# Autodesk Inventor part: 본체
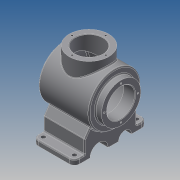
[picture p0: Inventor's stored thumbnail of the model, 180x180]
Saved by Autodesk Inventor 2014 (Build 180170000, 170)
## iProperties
Created: 2018-08
Part Number: 본체
Material: Generic
Document SubType Name: Modeling
Designer: kb542
Density: 1 g/cm^3
Appearance: Default
Author: kb542
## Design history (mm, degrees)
sketch "스케치1"
  geometry: L1 (-60, 0)-(60, 0); L2 (-60, 38)-(-48, 38); L3 (-48, 38)-(-48, 50); L4 (-48, 50)-(48.671, 50); L5 (42.163, 40)-(-38, 40); L6 (-38, 40)-(-38, 27); L7 (-38, 27)-(-60, 27); L8 (-60, 27)-(-60, 38); A1 r 116 centre (-56, 0) between (60, 0) and (48.671, 50); A2 r 106 centre (-56, 0) between (50, 0) and (42.163, 40); 2 further points
  constraints: 16 end point, 4 parallel, 4 point on circle, 3 perpendicular, 2 centre point, 2 point on line, 1 coincident, 1 horizontal, 1 midpoint, 1 vertical alignment
  dimensions: "d0" = 116 radius of A1; "d1" = 76 diameter of L2 L1; "d2" = 100 diameter of L4 L1; "d3" = 12 distance of L2.start L2.end; "d5" = 108 distance from line of L1.end L3; "d6" = 10 radial gap between concentric circles of A2 A1; "d7" = 54 diameter of L7 L1; "d8" = 80 diameter of L5 L1; "d9" = 22 distance of L6.end L7.end
revolve "회전1" sketch "스케치1" stored, may be unused: angle "d10" = 90 deg
node "작업 평면3"
sketch "스케치10"
  geometry: L1 (-40, 70)-(40, 70); L2 (40, 70)-(40, -70); L3 (40, -70)-(-40, -70); L4 (-40, -70)-(-40, 70); L5 (60, 38)-(60, -38) reference; 2 further points
  constraints: 8 end point, 2 parallel, 1 horizontal, 1 horizontal alignment, 1 midpoint, 1 perpendicular
  dimensions: "d89" = 140 distance of L3.end L1.start; "d90" = 80 distance of L1.start L1.end; "d91" = 20 distance between parallel lines of L5 L2
extrude "돌출6" join sketch "스케치10" distance "d92" = 10; taper "d93" = 0 deg
sketch "스케치11"
  geometry: L1 (0, 140)-(-10, 140) reference; L2 (-10, 0)-(-10, 140) reference; L3 (0, 0)-(-10, 0) reference; L4 (-10, 140)-(0, 140) reference; L5 (0, 140)-(0, 0) reference; L6 (0, 0)-(-10, 0) reference; L7 (-10, 0)-(-10, 140) reference; L8 (-51.154, 30.649)-(-35.946, 20); L9 (-35.946, 20)-(-10, 20); L10 (-51.154, 109.351)-(-35.946, 120); L11 (-35.946, 120)-(-10, 120); C1 r 27 at (-82, 70) reference; A1 r 50 centre (-82, 70) between (-51.154, 30.649) and (-51.154, 109.351) reference; 1 further point
  constraints: 8 end point, 2 perpendicular, 2 point on circle, 2 point on line, 2 vertical alignment
  dimensions: "d94" = 35 deg angle of L1 L10; "d95" = 35 deg angle of L3 L8; "d96" = 20 distance between parallel lines of L3 L9; "d97" = 20 distance between parallel lines of L11 L1
extrude "돌출7" join sketch "스케치11" distance "d98" = 80; taper "d99" = 0 deg
sketch "스케치13"
  geometry: L1 (0, 0)-(0, 140) reference; C1 r 12.5 at (0, 97.5); C2 r 17.5 at (0, 47.5); A1 r 50 centre (82, 70) between (51.154, 109.351) and (51.154, 30.649) reference
  constraints: 2 centre point, 2 point on line
  dimensions: "d100" = 12.5 radius of C1; "d101" = 17.5 radius of C2; "d102" = 22.5 vertical distance of C2.centre A1.centre; "d103" = 27.5 vertical distance of A1.centre C1.centre
extrude "돌출8" cut sketch "스케치13" stored distance "d104" = 80; taper "d105" = 0 deg
node "작업 평면5"
sketch "스케치15"
  geometry: L1 (60, 38)-(60, -38) reference; C1 r 38 at (-2, 0); 1 further point
  constraints: 1 centre point, 1 horizontal alignment
  dimensions: "d107" = 62 distance from line of L1 C1.centre; "d108" = 76 diameter of C1
extrude "돌출9" join sketch "스케치15" stored distance "d109" = 80; taper "d110" = 0 deg
sketch "스케치16"
  geometry: C1 r 38 at (0, 0) reference; C2 r 27 at (0, 0); 1 further point
  constraints: 1 centre point, 1 coincident
  dimensions: "d111" = 54 diameter of C2
extrude "돌출10" cut sketch "스케치16" stored distance "d112" = 80; taper "d113" = 0 deg
sketch "스케치17"
  geometry: C1 r 27 at (0, 0) reference; C2 r 38 at (0, 0) reference; A1 r 32.5 centre (0, 0) between (0, 32.5) and (32.5, 0); 3 further points
  constraints: 4 point on circle, 2 horizontal alignment, 2 vertical alignment, 1 centre point, 1 coincident
  dimensions: "d114" = 65 diameter of A1
hole "구멍4" sketch "스케치17" at (0, 32.5), (32.5, 0), (-32.5, 0), (0, -32.5) diameter "d115" = 3.459; stored, may be unused: countersink angle "d119" = 90 deg, drill point angle "d121" = 118 deg; dims "d116" = 8, "d117" = 4, "d118" = 2, "d120" = 10
sketch "스케치18"
  geometry: C1 r 38 at (0, 0) reference; C2 r 27 at (0, 0) reference; A1 r 32.5 centre (0, 0) between (0, 32.5) and (-32.5, 0); 2 further points
  constraints: 4 point on circle, 2 horizontal alignment, 2 vertical alignment, 1 centre point, 1 coincident
  dimensions: "d122" = 65 diameter of A1
hole "구멍5" sketch "스케치18" at (0, 32.5), (-32.5, 0), (32.5, 0), (0, -32.5) diameter "d123" = 3.459; stored, may be unused: countersink angle "d127" = 90 deg, drill point angle "d129" = 118 deg; dims "d124" = 8, "d125" = 4, "d126" = 2, "d128" = 10
fillet "모깎기2" dims "d130" = 10
sketch "스케치19"
  geometry: L1 (40, 60)-(40, 50) reference; L2 (40, 50)-(40, 35) reference; L3 (40, 35)-(-40, 35) reference; L4 (-40, 35)-(-40, 50) reference; L5 (-40, 50)-(40, 50) reference; L6 (-30, 70)-(30, 70) reference; L7 (-40, 50)-(-40, 60) reference; L8 (40, 20)-(40, -8.139) reference; L9 (40, -8.139)-(-40, -8.139) reference; L10 (-40, -8.139)-(-40, 20) reference; L11 (-40, 20)-(40, 20) reference; L12 (40, -36.861)-(40, -50) reference; L13 (40, -50)-(40, -60) reference; L14 (30, -70)-(-30, -70) reference; L15 (-40, -60)-(-40, -50) reference; L16 (40, -50)-(-40, -50) reference; L17 (-40, -36.861)-(40, -36.861) reference; L18 (-40, -50)-(-40, -36.861) reference; A1 r 10 centre (30, 60) between (40, 60) and (30, 70) reference; A2 r 10 centre (-30, 60) between (-30, 70) and (-40, 60) reference; A3 r 10 centre (30, -60) between (30, -70) and (40, -60) reference; A4 r 10 centre (-30, -60) between (-40, -60) and (-30, -70) reference; 5 further points
  constraints: 4 coincident
hole "구멍6" sketch "스케치19" at (-30, 60), (30, 60), (30, -60), (-30, -60) diameter "d131" = 8; stored, may be unused: countersink angle "d135" = 90 deg, drill point angle "d137" = 0 deg; dims "d132" = 8, "d133" = 4, "d134" = 2, "d136" = 10
node "작업 평면6"
sketch "스케치21"
  geometry: C1 r 32.5 at (0, 0); 1 further point
  constraints: 1 centre point, 1 coincident, 1 other
  dimensions: "d140" = 65 diameter of C1
feature "엠보싱1" sketch "스케치21" dims "d0" = 116, "d1" = 76, "d2" = 100, "d3" = 12, "d5" = 108, "d6" = 10, "d7" = 54, "d8" = 80, "d9" = 22, "d141" = 0.5, "d142" = 0
chamfer "모따기1" distance "d146" = 1; stored, may be unused: second distance "d147" = 2, angle "d148" = 45 deg
fillet "모깎기6" dims "d149" = 3
fillet "모깎기8" dims "d151" = 2
fillet "모깎기9" dims "d152" = 2
fillet "모깎기10" dims "d153" = 2
node "솔리드1"
node "절단 모서리 투영3"
node "절단 모서리 투영4"
other parameters: "d88" = -82, "d106" = 65
